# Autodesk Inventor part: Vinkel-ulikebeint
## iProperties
Author: Jan-Steinar
Shininess: 20.0
PropertySet Name: _Private Model Information
Created: 2001-01
Part Number: Vinkel-ulikebeint
Document SubType Name: Modeling
Designer: Jan-Steinar
Control State: 0
Master: False
Checked Out: False
PropertySet Name: Design Tracking Control
Density: 0.0
Volumn: 0.0
Area: 0.0
PropertySet Name: Model Information
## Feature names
1. Extrusion1
